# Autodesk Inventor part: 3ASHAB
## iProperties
Category: Hand Tools
Company: Mountain Blue Industries Ltd.
Manager: Charles Bliss
Shininess: 64.0
Length Units: 11272
Angle Units: 11279
Time Units: 11290
Mass Units: 11286
Length Display Precision: 3
Angle Display Precision: 2
Compacted: True
Part Number: 3ASHAB
Document SubType Name: Modeling
Created: 2004-02
Designer: QBZ
Material: Nylatron
Manufacturer: Standard
Standards Organization: Custom
Description: Mini Hook
Vendor: Snap-On Tools
Density: 0.0
Volumn: 0.0
Area: 0.0
PropertySet Name: Model Information
Control State: 0
Master: False
Checked Out: False
Length: 1
Author: QBZ
Revision Number: A
Title: Snap-On Mini Pick
Subject: Tools
Keywords: Pickset
Comments: Complete Set no. ASA204AB
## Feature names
1. Revolution1
2. Split1
3. Split2
4. Split3
5. Split4
6. Extrusion1
7. Circular Pattern1
8. Fillet1
9. Fillet2
10. Shank [Extrusion]
11. Srf Fillet1 [Fillet]
12. Srf Fillet2 [Fillet]
13. MultiPick Sweep
14. MultiPick Point [Fillet]
15. Hook Sweep
16. Hook Point [Fillet]
17. Straight Pick [Extrusion]
18. Straight Pick Chamfer [Chamfer]
19. Corner Pick
20. Corner Pick Fillet [Fillet]
